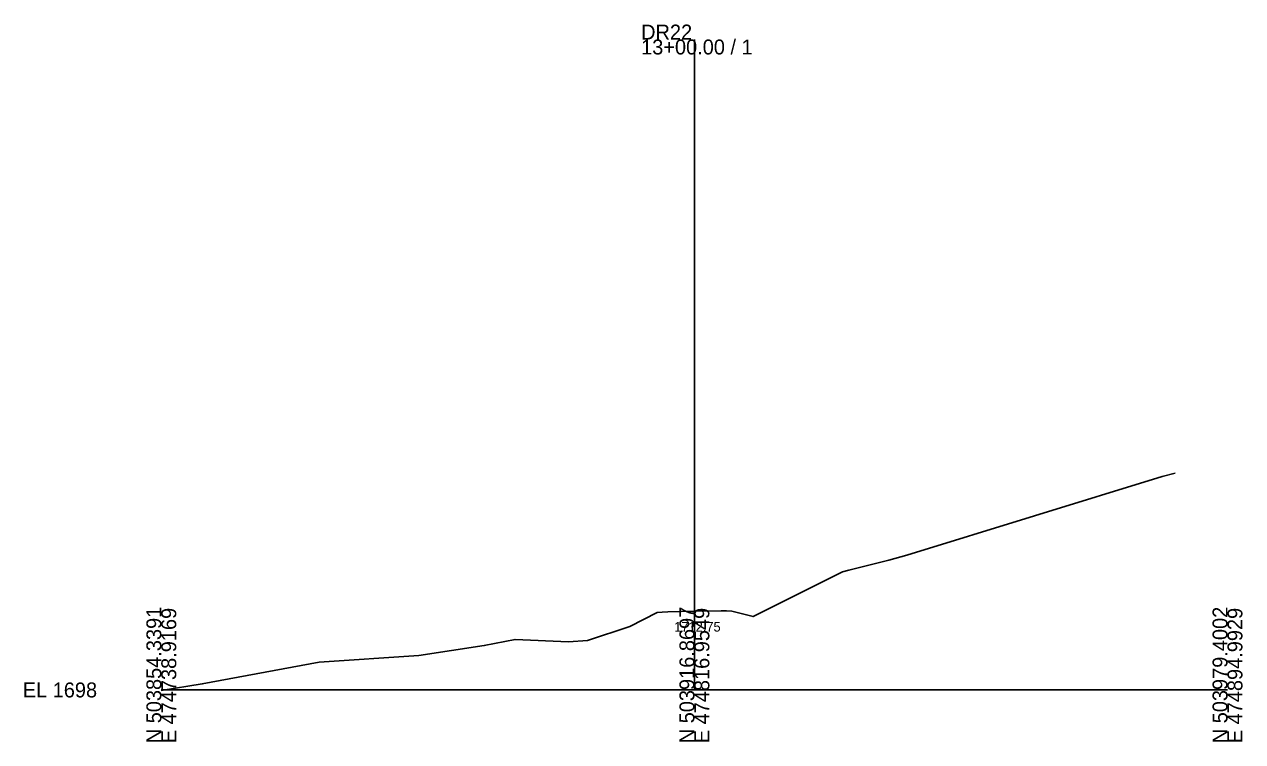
# Model space of a CAD drawing. Extents: x -26 to 1203, y -10 to 9633.
# Drawn here: x -25.7 to 202.8, y 7490.3 to 7624.8 of the extents above; entities that cross this region are included whole.
import ezdxf

# ---------------------------------------------------------------- set-up
doc = ezdxf.new("R2010")
doc.units = 0
for name, color, linetype in [('Exist Cross Section Cell', 7, 'Continuous'), ('Exist XS Center Line Elevation Label', 7, 'Continuous'), ('Exist XS Ground Line', 7, 'Continuous'), ('Scratch_Level_5', 7, 'Continuous')]:
    doc.layers.add(name, color=color, linetype=linetype)

msp = doc.modelspace()

# ---------------------------------------------------------------- linework, layer by layer
at = {"layer": 'Exist Cross Section Cell'}
for p, q in [((100, 7500), (100, 7622)), ((0, 7500), (100, 7500)), ((100, 7500), (200, 7500))]:
    msp.add_line(p, q, dxfattribs=at)
at = {"layer": 'Exist XS Ground Line'}
msp.add_lwpolyline([(0, 7499.87), (7.69, 7501.13), (29.6, 7505.19), (48.32, 7506.48), (60.59, 7508.31), (66.36, 7509.48), (76.4, 7509.02), (79.97, 7509.3), (87.86, 7511.92), (93.01, 7514.5), (93.98, 7514.57), (95, 7514.65), (100, 7514.75), (105, 7514.85), (106.02, 7514.81), (107, 7514.77), (111, 7513.77), (127.75, 7522.15), (128.94, 7522.45), (136.5, 7524.34), (139.85, 7525.27), (187.76, 7540.04), (190.21, 7540.67)], dxfattribs=at)
at = {"layer": 'Scratch_Level_5'}
msp.add_lwpolyline([(0, 7499.87), (7.69, 7501.13), (29.6, 7505.19), (48.32, 7506.48), (60.59, 7508.31), (66.36, 7509.48), (76.4, 7509.02), (79.97, 7509.3), (87.86, 7511.92), (93.01, 7514.5), (93.98, 7514.57), (95, 7514.65), (100, 7514.75), (105, 7514.85), (106.02, 7514.81), (107, 7514.77), (111, 7513.77), (127.75, 7522.15), (128.94, 7522.45), (136.5, 7524.34), (139.85, 7525.27), (187.76, 7540.04), (190.21, 7540.67)], dxfattribs=at)

# ---------------------------------------------------------------- texts
at = {"layer": 'Exist Cross Section Cell'}
for s, p in [('DR22', (90, 7622)), ('13+00.00 / 1', (90, 7619.2)), ('EL 1698', (-26, 7498.6))]:
    msp.add_text(s, height=2.8, dxfattribs=at).set_placement(p)
for s, p in [('N 503854.3391', (0, 7490)), ('E 474738.9169', (2.8, 7490)), ('N 503916.8697', (100, 7490)), ('E 474816.9549', (102.8, 7490)), ('N 503979.4002', (200, 7490)), ('E 474894.9929', (202.8, 7490))]:
    msp.add_text(s, height=2.8, rotation=90, dxfattribs=at).set_placement(p)
at = {"layer": 'Exist XS Center Line Elevation Label'}
msp.add_text('1712.75', height=1.8, dxfattribs=at).set_placement((96.22, 7510.95))

doc.saveas('drawing.dxf')
